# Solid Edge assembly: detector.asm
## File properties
Author: work
Template: Iso Assembly.asm
Last saved by: Lee
Revision: 232
Application: Solid Edge
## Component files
crane_mount.par
mirror_assembly.asm
Interference 8.par
mounting_bracket.par
mounting_bracket_mir.par
Interference 6.par
Interference 5.par
Interference 4.par
Interference 3.par
Interference 7.par
pmt.par
vessel.par
window.par
window_clamp.par
quartz_window.asm
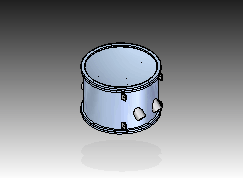
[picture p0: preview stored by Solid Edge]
